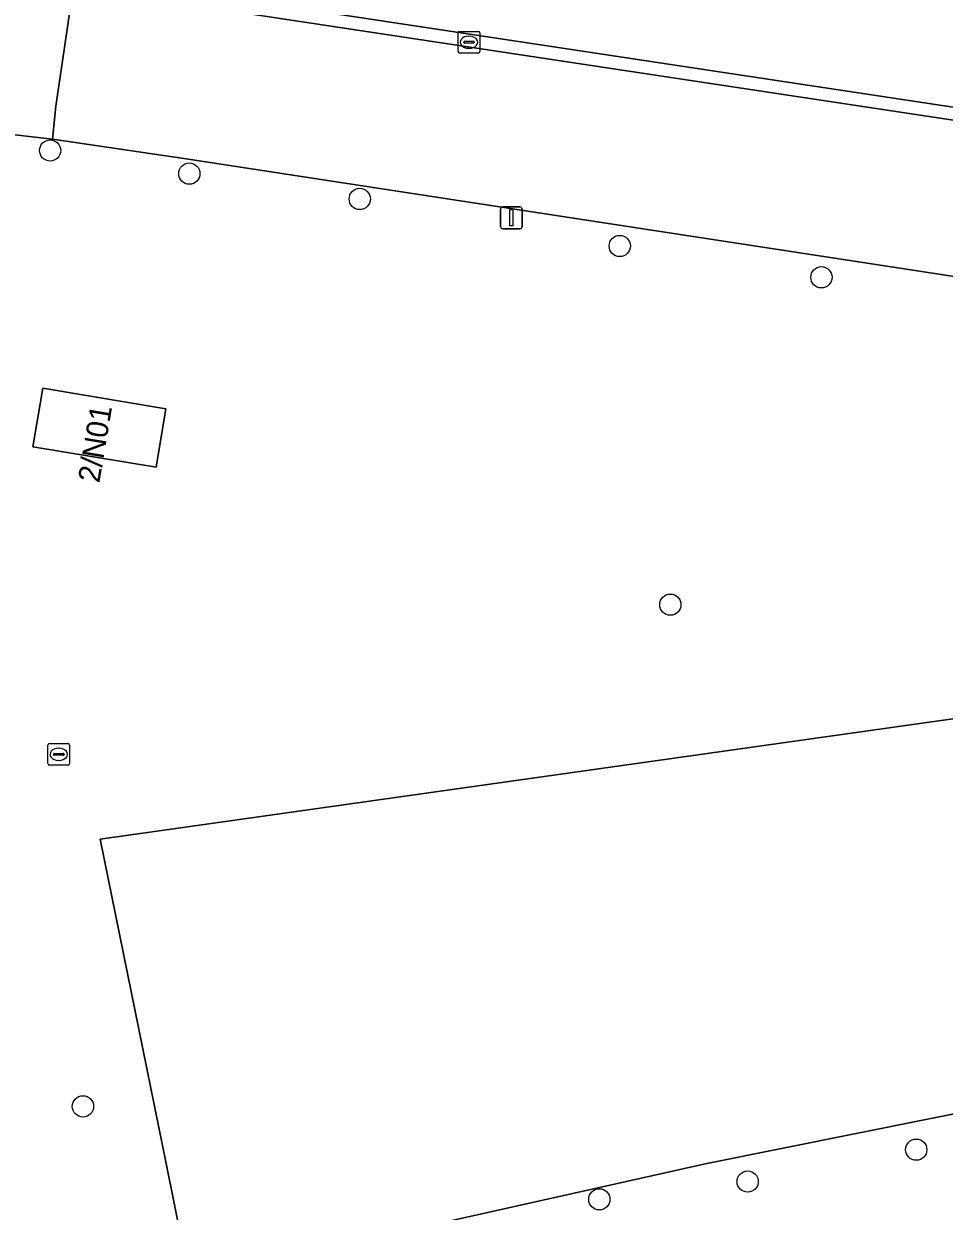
# Model space of a CAD drawing. Extents: x 160203 to 161530, y 379528 to 381797.
# Drawn here: x 160824.5 to 160866.8, y 380497.8 to 380552.4 of the extents above; entities that cross this region are included whole.
import ezdxf

# ---------------------------------------------------------------- set-up
doc = ezdxf.new("R2010")
doc.units = 0
for name, color, linetype in [('IMGEO_Boom', 7, 'Continuous'), ('IMGEO_Hek', 7, 'Continuous'), ('IMGEO_Kolk', 7, 'Continuous'), ('IMGEO_Lichtmast', 7, 'Continuous'), ('IMGEO_Loofbos', 7, 'Continuous'), ('IMGEO_Pand', 7, 'Continuous'), ('IMGEO_Pand_nummerreeks', 7, 'Continuous'), ('IMGEO_Parkeervlak_gesloten', 7, 'Continuous'), ('IMGEO_Rijbaan_lokaal_gesloten', 7, 'Continuous'), ('IMGEO_Rijbaan_lokaal_open', 7, 'Continuous'), ('IMGEO_Rioolput', 7, 'Continuous')]:
    doc.layers.add(name, color=color, linetype=linetype)

msp = doc.modelspace()

# ---------------------------------------------------------------- linework, layer by layer
at = {"layer": 'IMGEO_Boom'}
for centre in [(160825.731, 380546.573), (160832.132, 380545.511), (160839.97, 380544.344), (160851.927, 380542.182), (160861.201, 380540.743), (160854.25, 380525.69), (160827.24, 380502.618), (160865.56, 380500.628), (160857.809, 380499.164), (160850.985, 380498.346)]:
    msp.add_circle(centre, 0.489, dxfattribs=at)
at = {"layer": 'IMGEO_Hek'}
for points in [[(160951.518, 380519.182), (160951.456, 380519.19), (160855.926, 380500)], [(160855.926, 380500), (160832.145, 380494.674)]]:
    msp.add_lwpolyline(points, dxfattribs=at)
at = {"layer": 'IMGEO_Kolk'}
for p, q in [((160844.494, 380551.124), (160844.494, 380551.976)), ((160844.569, 380552.05), (160845.421, 380552.05)), ((160844.753, 380551.544), (160844.753, 380551.556)), ((160844.796, 380551.593), (160845.194, 380551.593)), ((160844.982, 380551.83), (160845.007, 380551.83)), ((160845.237, 380551.556), (160845.237, 380551.544)), ((160845.495, 380551.976), (160845.495, 380551.124)), ((160845.421, 380551.05), (160844.569, 380551.05)), ((160845.191, 380551.507), (160844.793, 380551.507)), ((160845.005, 380551.27), (160844.98, 380551.27))]:
    msp.add_line(p, q, dxfattribs=at)
for points in [[(160844.494, 380551.124), (160844.494, 380551.976)], [(160844.569, 380552.05), (160845.421, 380552.05)], [(160845.495, 380551.976), (160845.495, 380551.124)], [(160845.421, 380551.05), (160844.569, 380551.05)]]:
    msp.add_lwpolyline(points, dxfattribs=at)
for centre, radius, start, end in [((160844.571, 380551.974), 0.0765, 91.552, 178.448), ((160844.571, 380551.974), 0.0765, 91.552, 178.448), ((160844.793, 380551.553), 0.0403, 85.8775, 175.7526), ((160845.198, 380551.555), 0.0386, 1.7309, 96.639), ((160845.419, 380551.974), 0.0765, 1.552, 88.448), ((160845.419, 380551.974), 0.0765, 1.552, 88.448), ((160844.571, 380551.126), 0.0765, 181.552, 268.448), ((160844.571, 380551.126), 0.0765, 181.552, 268.448), ((160844.79, 380551.543), 0.0366, 178.938, 274.7102), ((160845.194, 380551.55), 0.043, 264.8664, 352.4533), ((160845.419, 380551.126), 0.0765, 271.552, 358.448), ((160845.419, 380551.126), 0.0765, 271.552, 358.448)]:
    msp.add_arc(centre, radius, start, end, dxfattribs=at)
for centre, major_axis, ratio, start_param, end_param in [((160844.981, 380551.55), (-0.387, 0.002), 0.722429, 4.712389, 7.853982), ((160845.006, 380551.55), (-0.39, 0.002), 0.717154, 1.570796, 4.712389)]:
    msp.add_ellipse(centre, major_axis=major_axis, ratio=ratio, start_param=start_param, end_param=end_param, dxfattribs=at)
at = {"layer": 'IMGEO_Lichtmast'}
for p, q in [((160846.546, 380543.978), (160847.336, 380543.978)), ((160847.336, 380543.978), (160846.546, 380543.978)), ((160846.446, 380543.078), (160846.446, 380543.878)), ((160846.446, 380543.878), (160846.446, 380543.078)), ((160847.436, 380543.878), (160847.436, 380543.078)), ((160847.436, 380543.078), (160847.436, 380543.878)), ((160847.336, 380542.978), (160846.546, 380542.978)), ((160846.546, 380542.978), (160847.336, 380542.978))]:
    msp.add_line(p, q, dxfattribs=at)
msp.add_lwpolyline([(160846.866, 380543.853), (160847.016, 380543.853), (160847.016, 380543.103), (160846.866, 380543.103), (160846.866, 380543.853)], dxfattribs=at)
for centre, start, end in [((160846.546, 380543.878), 90, 180), ((160846.546, 380543.878), 90, 180), ((160847.336, 380543.878), 0, 90), ((160847.336, 380543.878), 360, 90), ((160846.546, 380543.078), 180, 270), ((160846.546, 380543.078), 180, 270), ((160847.336, 380543.078), 270, 0), ((160847.336, 380543.078), 270, 0)]:
    msp.add_arc(centre, 0.1, start, end, dxfattribs=at)
at = {"layer": 'IMGEO_Loofbos'}
for points in [[(160923.009, 380526.579), (160955.011, 380521.483), (160954.687, 380518.782), (160963.792, 380517.634), (160965.031, 380525.91), (160911.436, 380534.021), (160831.991, 380546.196), (160825.841, 380547.097), (160821.176, 380547.625), (160821.039, 380547.637)], [(160820.338, 380511.651), (160824.092, 380492.861), (160831.887, 380494.616), (160832.145, 380494.674), (160831.064, 380500), (160828.037, 380514.908), (160874.529, 380521.462), (160876.82, 380510.174), (160917.453, 380518.109), (160923.009, 380526.579)]]:
    msp.add_lwpolyline(points, dxfattribs=at)
for points in [[(160830.608, 380532.01), (160824.942, 380532.951), (160825.388, 380535.638), (160831.054, 380534.697)], [(160855.926, 380500), (160951.456, 380519.19), (160951.518, 380519.182), (160951.934, 380519.13), (160953.58, 380518.922), (160954.687, 380518.782), (160955.011, 380521.483), (160923.009, 380526.579), (160917.453, 380518.109), (160876.82, 380510.174), (160874.529, 380521.462), (160828.037, 380514.908), (160831.064, 380500), (160832.145, 380494.674)], [(160833.499, 380489.33), (160833.56, 380489.783), (160833.852, 380490.316), (160834.2, 380490.611), (160834.638, 380490.788), (160879.901, 380499.518), (160902.101, 380503.8), (160944.615, 380512.001), (160946.869, 380502.452), (160954.812, 380504.084), (160951.934, 380519.13), (160951.518, 380519.182), (160951.456, 380519.19), (160855.926, 380500), (160832.145, 380494.674), (160831.887, 380494.616), (160862.461, 380342.515), (160863.045, 380342.63)]]:
    msp.add_lwpolyline(points, close=True, dxfattribs=at)
at = {"layer": 'IMGEO_Pand'}
msp.add_lwpolyline([(160830.608, 380532.01), (160831.054, 380534.697), (160825.388, 380535.638), (160824.942, 380532.951)], close=True, dxfattribs=at)
at = {"layer": 'IMGEO_Parkeervlak_gesloten'}
msp.add_lwpolyline([(161024.98, 380529.951), (161000, 380533.651), (160940.686, 380542.511), (160845.744, 380556.692), (160833.175, 380558.569), (160830.154, 380559), (160828.405, 380559.25), (160827.637, 380559.36), (160827.221, 380554.627), (160828.18, 380554.482), (161000, 380528.513), (161026.173, 380524.441), (161026.899, 380529.633)], close=True, dxfattribs=at)
at = {"layer": 'IMGEO_Rijbaan_lokaal_gesloten'}
msp.add_lwpolyline([(160812.565, 380548.307), (160821.039, 380547.637), (160821.176, 380547.625), (160825.841, 380547.097), (160825.987, 380548.612), (160826.76, 380553.818)], dxfattribs=at)
at = {"layer": 'IMGEO_Rijbaan_lokaal_open'}
for points in [[(160826.75, 380554.296), (160826.76, 380553.818), (160825.987, 380548.612), (160825.841, 380547.097), (160831.991, 380546.196), (160911.436, 380534.021), (160965.031, 380525.91), (160970.441, 380525.091), (161000, 380520.618), (161026.638, 380516.587), (161027.779, 380523.619), (161026.094, 380523.879), (161000, 380527.913), (160828.089, 380553.895)], [(161026.173, 380524.441), (161000, 380528.513), (160828.18, 380554.482), (160828.089, 380553.895), (161000, 380527.913), (161026.094, 380523.879)]]:
    msp.add_lwpolyline(points, close=True, dxfattribs=at)
at = {"layer": 'IMGEO_Rioolput'}
for p, q in [((160825.627, 380518.383), (160825.627, 380519.235)), ((160825.702, 380519.309), (160826.554, 380519.309)), ((160825.886, 380518.803), (160825.886, 380518.815)), ((160825.929, 380518.852), (160826.327, 380518.852)), ((160826.115, 380519.089), (160826.14, 380519.089)), ((160826.37, 380518.815), (160826.37, 380518.803)), ((160826.628, 380519.235), (160826.628, 380518.383)), ((160826.554, 380518.309), (160825.702, 380518.309)), ((160826.324, 380518.766), (160825.926, 380518.766)), ((160826.138, 380518.529), (160826.113, 380518.529))]:
    msp.add_line(p, q, dxfattribs=at)
for points in [[(160825.627, 380518.383), (160825.627, 380519.235)], [(160825.702, 380519.309), (160826.554, 380519.309)], [(160826.628, 380519.235), (160826.628, 380518.383)], [(160826.554, 380518.309), (160825.702, 380518.309)]]:
    msp.add_lwpolyline(points, dxfattribs=at)
for centre, radius, start, end in [((160825.704, 380519.233), 0.0765, 91.552, 178.448), ((160825.704, 380519.233), 0.0765, 91.552, 178.448), ((160825.926, 380518.812), 0.0403, 85.8775, 175.7526), ((160825.923, 380518.802), 0.0366, 178.938, 274.7102), ((160826.327, 380518.809), 0.043, 264.8664, 352.4533), ((160826.331, 380518.814), 0.0386, 1.7309, 96.639), ((160826.552, 380519.233), 0.0765, 1.552, 88.448), ((160826.552, 380519.233), 0.0765, 1.552, 88.448), ((160825.704, 380518.385), 0.0765, 181.552, 268.448), ((160825.704, 380518.385), 0.0765, 181.552, 268.448), ((160826.552, 380518.385), 0.0765, 271.552, 358.448), ((160826.552, 380518.385), 0.0765, 271.552, 358.448)]:
    msp.add_arc(centre, radius, start, end, dxfattribs=at)
for centre, major_axis, ratio, start_param, end_param in [((160826.114, 380518.809), (-0.387, 0.002), 0.722429, 4.712389, 7.853982), ((160826.139, 380518.809), (-0.39, 0.002), 0.717154, 1.570796, 4.712389)]:
    msp.add_ellipse(centre, major_axis=major_axis, ratio=ratio, start_param=start_param, end_param=end_param, dxfattribs=at)

# ---------------------------------------------------------------- texts
at = {"layer": 'IMGEO_Pand_nummerreeks'}
msp.add_text('2/N01', height=1, rotation=80.4399, dxfattribs=at).set_placement((160827.991, 380531.254))

doc.saveas('drawing.dxf')
